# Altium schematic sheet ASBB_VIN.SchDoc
size A4
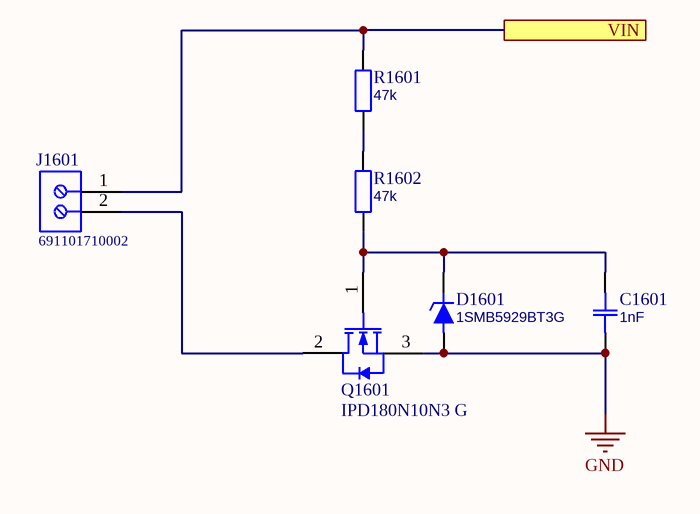
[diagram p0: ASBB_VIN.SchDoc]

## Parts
C1601  1nF  [0603]
D1601  1SMB5929BT3G  [SMB]
J1601  691101710002  [691101710002]
Q1601  IPD180N10N3 G  [INF-PG-TO252-3-11_A_N]
R1601  47k  [0603]
R1602  47k  [0603]

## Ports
VIN

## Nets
GND: C1601.2 D1601.2(A) Q1601.3(SOURCE)
VIN: J1601.1 R1601.2 ; port VIN
NetC1601_1: C1601.1 D1601.1(C) Q1601.1(GATE) R1602.1
NetJ1601_2: J1601.2 Q1601.2(DRAIN)
NetR1601_1: R1601.1 R1602.2

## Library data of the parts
C1601 = Capacitor
D1601 = Diode Zener: Zener Diode / Varistor unipolar
J1601 = 691101710002: Series 101 - 5.00 mm Horizontal Entry Modular with Pressure Clamp WR-TBL, 2 pin; Pin Number: 2; Pitch: 5.00 mm
Q1601 = IPD180N10N3 G: N-Channel OptiMOS 3 Power-Transistor, 100 V VDS, 43 A ID, -55 to 175 degC, PG-TO252-3-11, Reel, Green; Manufacturer: Infineon; Green: TRUE; ID (max): 43 A; IDpuls (max): 172 A; Polarity: N; Ptot (max): 71 W; QG: 19 nC; RDS (on) (max): 18 mOhm; Rth: 2.1 K/W; RthJA (max): 75 K/W; VDS (max): 100 V; VGS(th) (max): 3.5 V; VGS(th) (min): 2 V
R1601 R1602 = Resistor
